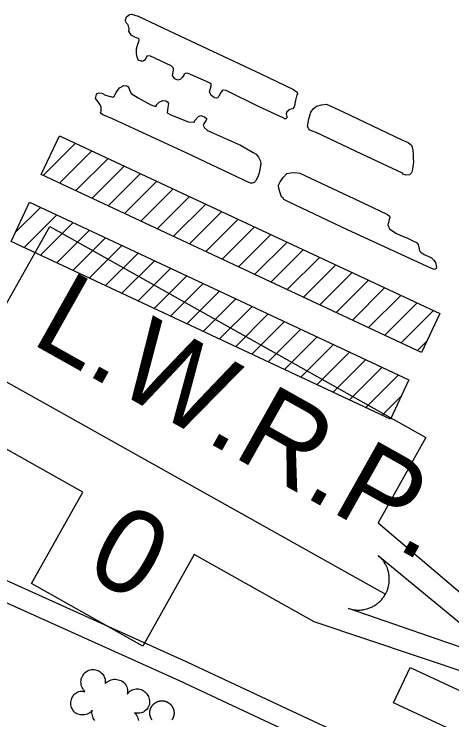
# Model space of a CAD drawing. Extents: x 3704301 to 3742427, y 506229 to 532009.
# Drawn here: x 3708834 to 3709482, y 524550 to 525595 of the extents above; entities that cross this region are included whole.
import ezdxf

# ---------------------------------------------------------------- set-up
doc = ezdxf.new("R2010")
doc.units = 0
for name, color, linetype in [('V-BLDG-OTLN', 7, 'Continuous'), ('V-ROAD-CNTR', 7, 'Continuous'), ('V-SITE-STRC', 7, 'Continuous'), ('V-TOPO-SHOR', 7, 'Continuous'), ('V-TOPO-WATR-IDEN', 7, 'Continuous')]:
    doc.layers.add(name, color=color, linetype=linetype)

msp = doc.modelspace()

# ---------------------------------------------------------------- linework, layer by layer
at = {"layer": 'V-BLDG-OTLN'}
for p, q in [((3708876.9, 525356.5), (3708924.6, 525404.2)), ((3708901, 525345.2), (3708948.7, 525392.9)), ((3708925.1, 525334), (3708972.8, 525381.7)), ((3708949.2, 525322.7), (3708996.9, 525370.4)), ((3708973.2, 525311.4), (3709020.9, 525359.1)), ((3708997.3, 525300.1), (3709045, 525347.8)), ((3709021.4, 525288.9), (3709069.1, 525336.6)), ((3709045.5, 525277.6), (3709093.2, 525325.3)), ((3709069.6, 525266.3), (3709117.3, 525314)), ((3708835.6, 525271.8), (3708872.9, 525309.2)), ((3709093.6, 525255.1), (3709141.3, 525302.8)), ((3708848.7, 525249.6), (3708897, 525297.9)), ((3709117.7, 525243.8), (3709165.4, 525291.5)), ((3708872.8, 525238.3), (3708921.1, 525286.6)), ((3709141.8, 525232.5), (3709189.5, 525280.2)), ((3708896.9, 525227), (3708945.2, 525275.3)), ((3708920.9, 525215.8), (3708969.2, 525264.1)), ((3709165.9, 525221.2), (3709213.6, 525268.9)), ((3708945, 525204.5), (3708993.3, 525252.8)), ((3709190, 525210), (3709237.7, 525257.7)), ((3708969.1, 525193.2), (3709017.4, 525241.5)), ((3709214.1, 525198.7), (3709261.8, 525246.4)), ((3708993.2, 525181.9), (3709041.5, 525230.2)), ((3709238.1, 525187.4), (3709285.8, 525235.1)), ((3709017.2, 525170.6), (3709065.5, 525218.9)), ((3709262.2, 525176.1), (3709309.9, 525223.8)), ((3709041.3, 525159.4), (3709089.6, 525207.7)), ((3709286.3, 525164.9), (3709334, 525212.6)), ((3709065.4, 525148.1), (3709113.7, 525196.4)), ((3709310.4, 525153.6), (3709358.1, 525201.3)), ((3709334.5, 525142.3), (3709382.2, 525190)), ((3709089.5, 525136.8), (3709137.8, 525185.1)), ((3709358.5, 525131), (3709406.2, 525178.7)), ((3709113.6, 525125.5), (3709161.9, 525173.8)), ((3709382.6, 525119.8), (3709430.3, 525167.5)), ((3709137.6, 525114.2), (3709185.9, 525162.5)), ((3709406.7, 525108.5), (3709454.4, 525156.2)), ((3709161.7, 525103), (3709210, 525151.3)), ((3709185.8, 525091.7), (3709234.1, 525140)), ((3709209.9, 525080.4), (3709258.2, 525128.7)), ((3709233.9, 525069.1), (3709282.2, 525117.4)), ((3709258, 525057.8), (3709306.3, 525106.2)), ((3709430.8, 525097.2), (3709444.7, 525111.1)), ((3709282.1, 525046.6), (3709330.4, 525094.9)), ((3709306.2, 525035.3), (3709354.5, 525083.6)), ((3709330.2, 525024), (3709378.5, 525072.3)), ((3709354.3, 525012.7), (3709402.6, 525061)), ((3709378.4, 525001.5), (3709406.9, 525030))]:
    msp.add_line(p, q, dxfattribs=at)
for points in [[(3709436.9, 525094.4), (3708874, 525357.9), (3708900.9, 525415.3), (3709463.8, 525151.8)], [(3709390.8, 524995.6), (3708829.4, 525258.6), (3708856.7, 525316.8), (3709418.1, 525053.8)], [(3709834.5, 524370.9), (3709395.4, 524575.2), (3709419.8, 524627.6), (3709858.8, 524423.3)]]:
    msp.add_lwpolyline(points, close=True, dxfattribs=at)
at = {"layer": 'V-ROAD-CNTR'}
for points in [[(3708720.9, 524802.3), (3709090.6, 524635.4), (3709485.6, 524450.5), (3709632.3, 524381.8), (3709704.7, 524349.8), (3709748.3, 524342.7), (3709809.3, 524355.6), (3709858.9, 524401.9), (3709903.2, 524473.9), (3709957, 524574.5), (3709982.2, 524650), (3709981.6, 524658.2), (3709966.1, 524672.8), (3709920, 524693.9), (3709756.7, 524768), (3709527.1, 524884)], [(3708708.6, 524774.9), (3709078.1, 524608.1), (3709472.9, 524423.3), (3709619.9, 524354.5), (3709696.1, 524320.8), (3709749, 524312.2), (3709823.6, 524328), (3709882.3, 524382.7), (3709929.2, 524459), (3709984.7, 524562.5), (3710012.6, 524646.3), (3710010.6, 524672.1), (3709983, 524698.1), (3709932.5, 524721.2), (3709769.7, 524795.1), (3709727, 524816.6)]]:
    msp.add_lwpolyline(points, dxfattribs=at)
at = {"layer": 'V-SITE-STRC'}
for points in [[(3708933.2, 524592.5), (3708934.9, 524592.4), (3708936.6, 524592.2), (3708938.3, 524591.7), (3708937.9, 524593.1), (3708936.5, 524594.6), (3708935.4, 524596.3), (3708934.4, 524598.1), (3708933.7, 524600), (3708933.1, 524601.9), (3708932.8, 524603.9), (3708932.7, 524606), (3708932.8, 524608), (3708933.1, 524610), (3708933.6, 524611.9), (3708934.4, 524613.8), (3708935.3, 524615.6), (3708936.4, 524617.3), (3708937.7, 524618.9), (3708939.2, 524620.3), (3708940.8, 524621.5), (3708942.5, 524622.6), (3708944.4, 524623.4), (3708946.3, 524624.1), (3708948.3, 524624.6), (3708950.2, 524624.7), (3708952.2, 524624.6), (3708954.2, 524624.3), (3708956.1, 524623.8), (3708957.9, 524623.1), (3708959.7, 524622.2), (3708961.3, 524621.1), (3708962.8, 524619.8), (3708964.2, 524618.4), (3708965.4, 524616.8), (3708966.5, 524615.1), (3708967.3, 524613.3), (3708967.9, 524611.5), (3708968.4, 524609.5), (3708968.6, 524607.6), (3708968.6, 524605.6), (3708968.4, 524603.6), (3708969.9, 524605.1), (3708971.6, 524606.4), (3708973.4, 524607.5), (3708975.3, 524608.5), (3708977.3, 524609.2), (3708979.4, 524609.7), (3708981.5, 524610), (3708983.6, 524610.1), (3708985.7, 524609.9), (3708987.8, 524609.5), (3708989.9, 524609), (3708991.8, 524608.2), (3708993.7, 524607.2), (3708995.5, 524606), (3708997.1, 524604.6), (3708998.4, 524602.9), (3708999.5, 524601), (3709000.4, 524599), (3709001, 524596.9), (3709001.4, 524594.7), (3709001.6, 524592.6), (3709001.5, 524590.4), (3709001.2, 524588.2), (3709002.4, 524589.7), (3709003.8, 524591.1), (3709005.3, 524592.4), (3709006.9, 524593.4), (3709008.6, 524594.3), (3709010.4, 524595), (3709012.3, 524595.5), (3709014.2, 524595.8), (3709016.2, 524595.8), (3709018.1, 524595.7), (3709020, 524595.3), (3709021.9, 524594.8), (3709023.7, 524594), (3709025.3, 524593.1), (3709026.9, 524592), (3709028.4, 524590.7), (3709029.7, 524589.3), (3709030.8, 524587.7), (3709031.8, 524586), (3709032.7, 524584.4), (3709033.4, 524582.6), (3709033.9, 524580.8), (3709034.3, 524578.9), (3709034.4, 524577), (3709034.3, 524575.2), (3709034, 524573.3), (3709033.5, 524571.5), (3709032.8, 524569.7), (3709031.9, 524568), (3709030.9, 524566.5), (3709029.6, 524565), (3709028.3, 524563.7), (3709026.7, 524562.6), (3709025.1, 524561.6), (3709023.4, 524560.9)], [(3708953.2, 524549.2), (3708952, 524550.9), (3708951, 524552.6), (3708950.2, 524554.5), (3708949.6, 524556.4), (3708949.2, 524558.4), (3708949, 524560.4), (3708949.1, 524562.4), (3708949.3, 524564.4), (3708948.5, 524562.9), (3708947.5, 524561.5), (3708945.8, 524560.4), (3708944, 524559.4), (3708942.1, 524558.6), (3708940.1, 524558), (3708938.1, 524557.6), (3708936.1, 524557.3), (3708934, 524557.3), (3708932, 524557.5), (3708930, 524557.9), (3708928, 524558.5), (3708926.1, 524559.3), (3708924.3, 524560.2), (3708922.8, 524561.6), (3708921.6, 524563.1), (3708920.5, 524564.8), (3708919.5, 524566.6), (3708918.8, 524568.4), (3708918.2, 524570.3), (3708917.9, 524572.3), (3708917.8, 524574.2), (3708917.8, 524576.2), (3708918.1, 524578.2), (3708918.6, 524580.1), (3708919.2, 524582), (3708920.1, 524583.8), (3708921.2, 524585.5), (3708922.4, 524587.1), (3708923.8, 524588.5), (3708925.1, 524589.6), (3708926.5, 524590.6), (3708928.1, 524591.3), (3708929.7, 524591.9), (3708931.4, 524592.3), (3708933.2, 524592.5)], [(3709034.6, 524560.1), (3709034.6, 524560.5), (3709034.7, 524560.8), (3709034.7, 524561.1), (3709034.7, 524561.4), (3709034.7, 524561.7), (3709034.7, 524562), (3709034.8, 524562.3), (3709034.8, 524562.6), (3709034.9, 524562.9), (3709034.9, 524563.3), (3709035, 524563.6), (3709035, 524563.9), (3709035.1, 524564.2), (3709035.2, 524564.5), (3709035.2, 524564.8), (3709035.3, 524565.1), (3709035.4, 524565.4), (3709035.5, 524565.7), (3709035.6, 524566), (3709035.7, 524566.3), (3709035.8, 524566.6), (3709035.9, 524566.9), (3709036, 524567.2), (3709036.1, 524567.4), (3709036.3, 524567.7), (3709036.4, 524568), (3709036.5, 524568.3), (3709036.7, 524568.6), (3709036.8, 524568.8), (3709037, 524569.1), (3709037.1, 524569.4), (3709037.3, 524569.7), (3709037.5, 524569.9), (3709037.6, 524570.2), (3709037.8, 524570.4), (3709038, 524570.7), (3709038.2, 524571), (3709038.4, 524571.2), (3709038.6, 524571.4), (3709038.8, 524571.7), (3709039, 524571.9), (3709039.2, 524572.2), (3709039.4, 524572.4), (3709039.6, 524572.6), (3709039.8, 524572.9), (3709040, 524573.1), (3709040.3, 524573.3), (3709040.5, 524573.5), (3709040.7, 524573.7), (3709041, 524573.9), (3709041.2, 524574.1), (3709041.4, 524574.3), (3709041.7, 524574.5), (3709041.9, 524574.7), (3709042.2, 524574.9), (3709042.5, 524575.1), (3709042.7, 524575.2), (3709043, 524575.4), (3709043.2, 524575.6), (3709043.5, 524575.7)], [(3709043.5, 524575.7), (3709043.8, 524575.9), (3709044.1, 524576), (3709044.3, 524576.2), (3709044.6, 524576.3), (3709044.9, 524576.5), (3709045.2, 524576.6), (3709045.5, 524576.7), (3709045.7, 524576.8), (3709046, 524577), (3709046.3, 524577.1), (3709046.6, 524577.2), (3709046.9, 524577.3), (3709047.2, 524577.4), (3709047.5, 524577.5), (3709047.8, 524577.5), (3709048.1, 524577.6), (3709048.4, 524577.7), (3709048.7, 524577.8), (3709049, 524577.8), (3709049.3, 524577.9), (3709049.7, 524577.9), (3709050, 524578), (3709050.3, 524578), (3709050.6, 524578.1), (3709050.9, 524578.1), (3709051.2, 524578.1), (3709051.5, 524578.2), (3709051.8, 524578.2), (3709052.1, 524578.2), (3709052.5, 524578.2), (3709052.8, 524578.2), (3709053.1, 524578.2), (3709053.4, 524578.2), (3709053.7, 524578.2), (3709054, 524578.1), (3709054.3, 524578.1), (3709054.6, 524578.1), (3709054.9, 524578), (3709055.3, 524578), (3709055.6, 524577.9), (3709055.9, 524577.9), (3709056.2, 524577.8), (3709056.5, 524577.8), (3709056.8, 524577.7), (3709057.1, 524577.6), (3709057.4, 524577.5), (3709057.7, 524577.4), (3709058, 524577.3), (3709058.3, 524577.2), (3709058.6, 524577.1), (3709058.9, 524577), (3709059.2, 524576.9), (3709059.5, 524576.8), (3709059.8, 524576.7), (3709060, 524576.6), (3709060.3, 524576.4), (3709060.6, 524576.3), (3709060.9, 524576.1), (3709061.2, 524576), (3709061.4, 524575.8), (3709061.7, 524575.7), (3709062, 524575.5), (3709062.2, 524575.4), (3709062.5, 524575.2), (3709062.8, 524575), (3709063, 524574.8), (3709063.3, 524574.7), (3709063.5, 524574.5), (3709063.8, 524574.3), (3709064, 524574.1), (3709064.2, 524573.9), (3709064.5, 524573.7), (3709064.7, 524573.5), (3709064.9, 524573.2), (3709065.2, 524573), (3709065.4, 524572.8), (3709065.6, 524572.6), (3709065.8, 524572.3), (3709066, 524572.1), (3709066.2, 524571.9), (3709066.4, 524571.6), (3709066.6, 524571.4), (3709066.8, 524571.1), (3709067, 524570.9), (3709067.2, 524570.6), (3709067.4, 524570.4), (3709067.5, 524570.1), (3709067.7, 524569.9), (3709067.9, 524569.6), (3709068, 524569.3), (3709068.2, 524569.1), (3709068.3, 524568.8), (3709068.5, 524568.5), (3709068.6, 524568.2), (3709068.8, 524567.9), (3709068.9, 524567.7), (3709069, 524567.4), (3709069.1, 524567.1), (3709069.3, 524566.8), (3709069.4, 524566.5)], [(3709023.4, 524560.9), (3709021.6, 524560.3), (3709019.7, 524559.9), (3709017.9, 524559.7), (3709016, 524559.8), (3709014.1, 524560), (3709012.2, 524560.4), (3709013.7, 524558.8), (3709014.9, 524557), (3709016, 524555.1), (3709016.8, 524553.2), (3709017.5, 524551.1), (3709017.9, 524549)], [(3709038, 524549.9), (3709037.8, 524550.1), (3709037.6, 524550.4), (3709037.4, 524550.7), (3709037.3, 524550.9), (3709037.1, 524551.2), (3709037, 524551.5), (3709036.8, 524551.7), (3709036.7, 524552), (3709036.5, 524552.3), (3709036.4, 524552.6), (3709036.2, 524552.9), (3709036.1, 524553.1), (3709036, 524553.4), (3709035.9, 524553.7), (3709035.8, 524554), (3709035.7, 524554.3), (3709035.6, 524554.6), (3709035.5, 524554.9), (3709035.4, 524555.2), (3709035.3, 524555.5), (3709035.2, 524555.8), (3709035.1, 524556.1), (3709035.1, 524556.4), (3709035, 524556.7), (3709034.9, 524557), (3709034.9, 524557.3), (3709034.8, 524557.6), (3709034.8, 524558), (3709034.8, 524558.3), (3709034.7, 524558.6), (3709034.7, 524558.9), (3709034.7, 524559.2), (3709034.7, 524559.5), (3709034.7, 524559.8), (3709034.6, 524560.1)], [(3709069.4, 524566.5), (3709069.5, 524566.2), (3709069.6, 524565.9), (3709069.7, 524565.6), (3709069.8, 524565.3), (3709069.9, 524565), (3709069.9, 524564.7), (3709070, 524564.4), (3709070.1, 524564.1), (3709070.1, 524563.8), (3709070.2, 524563.5), (3709070.3, 524563.2), (3709070.3, 524562.9), (3709070.4, 524562.6), (3709070.4, 524562.3), (3709070.4, 524561.9), (3709070.4, 524561.6), (3709070.5, 524561.3), (3709070.5, 524561), (3709070.5, 524560.7), (3709070.5, 524560.4), (3709070.5, 524560.1), (3709070.5, 524559.8), (3709070.5, 524559.4), (3709070.5, 524559.1), (3709070.4, 524558.8), (3709070.4, 524558.5), (3709070.4, 524558.2), (3709070.3, 524557.9), (3709070.3, 524557.6), (3709070.2, 524557.3), (3709070.2, 524557), (3709070.1, 524556.7), (3709070.1, 524556.3), (3709070, 524556), (3709069.9, 524555.7), (3709069.8, 524555.4), (3709069.8, 524555.1), (3709069.7, 524554.8), (3709069.6, 524554.5), (3709069.5, 524554.2), (3709069.4, 524554), (3709069.2, 524553.7), (3709069.1, 524553.4), (3709069, 524553.1), (3709068.9, 524552.8), (3709068.7, 524552.5), (3709068.6, 524552.2), (3709068.5, 524552), (3709068.3, 524551.7), (3709068.2, 524551.4), (3709068, 524551.1), (3709067.8, 524550.9), (3709067.7, 524550.6), (3709067.5, 524550.3), (3709067.3, 524550.1), (3709067.1, 524549.8)]]:
    msp.add_lwpolyline(points, dxfattribs=at)
at = {"layer": 'V-TOPO-SHOR'}
for points in [[(3709232.9, 525441.4), (3709195.5, 525458.8), (3709147.7, 525482.3), (3709143, 525482.8), (3709141.6, 525481.8), (3709139.2, 525479), (3709136.9, 525473.3), (3709135, 525471.4), (3709133.1, 525470.9), (3709130.2, 525471.4), (3709129.3, 525472.3), (3709125.5, 525475.1), (3709123.1, 525480.3), (3709125.5, 525489.3), (3709125.5, 525491.7), (3709123.1, 525493.6), (3709090.4, 525508.2), (3709087.1, 525507.7), (3709085.2, 525506.7), (3709084.8, 525504.8), (3709082.4, 525501.5), (3709080, 525499.2), (3709076.7, 525497.7), (3709073.4, 525498.7), (3709071.5, 525499.6), (3709068.2, 525504.3), (3709069.6, 525512.4), (3709069.6, 525515.2), (3709068.7, 525516.6), (3709066.3, 525519), (3709034.6, 525533.6), (3709030.3, 525533.1), (3709029.4, 525530.7), (3709028.9, 525529.8), (3709026.5, 525526.9), (3709024.7, 525525.5), (3709021.8, 525525.5), (3709020.4, 525526), (3709018, 525526.9), (3709016.1, 525531.6), (3709014.7, 525537.3), (3709014.7, 525543.9), (3709016.6, 525549.6), (3709018.4, 525554.8), (3709018.9, 525557.2), (3709018, 525559.1), (3709013.7, 525560.9), (3709007.1, 525564.2), (3709003.7, 525570.4), (3709004.2, 525573.7), (3709003.2, 525577.9), (3709002.3, 525580.3), (3708999.9, 525582.2), (3708998, 525586), (3708998.5, 525586.4), (3708999.9, 525591.2), (3709004.6, 525595), (3709007.5, 525595.4), (3709017.4, 525592.2), (3709071.8, 525566.8), (3709198.7, 525507), (3709247.5, 525483.9), (3709252.7, 525479.7), (3709253.2, 525477.3), (3709252.2, 525475.9), (3709250.4, 525467.9), (3709249.9, 525464.6), (3709249.4, 525463.6), (3709249.4, 525461.7), (3709248.5, 525457.9), (3709245.7, 525455.1), (3709241.9, 525454.1), (3709237.6, 525450.8), (3709236.2, 525447.5), (3709237.6, 525443.7), (3709237.6, 525441.8), (3709235.8, 525440.4), (3709234.3, 525440.4), (3709233.9, 525440.4), (3709232.9, 525441.4)], [(3709181.1, 525346.2), (3709088.3, 525389.9), (3708979.5, 525440.3), (3708965.3, 525446.4), (3708962.9, 525447.8), (3708961.9, 525449.7), (3708962.4, 525451.6), (3708962.4, 525457.7), (3708961.4, 525461), (3708958.1, 525465.3), (3708954.3, 525470.5), (3708955.7, 525476.2), (3708956.7, 525477.6), (3708959, 525479), (3708963.8, 525478.5), (3708969, 525475.2), (3708979.9, 525472.4), (3708981.7, 525473.9), (3708984.6, 525479.1), (3708989.8, 525486.2), (3708996.4, 525489.5), (3709000.6, 525489), (3709002, 525488.1), (3709003.5, 525486.2), (3709004.4, 525483.4), (3709006.8, 525477.7), (3709017.2, 525471.6), (3709036.2, 525461.2), (3709043.3, 525458.4), (3709044.7, 525460.3), (3709044.7, 525461.2), (3709048.4, 525465), (3709054.1, 525467.4), (3709058.4, 525466.9), (3709060.7, 525465.5), (3709062.2, 525463.2), (3709061.7, 525459.9), (3709061.2, 525457), (3709060.3, 525449.4), (3709065.5, 525446.2), (3709091.5, 525435.8), (3709100.5, 525435.4), (3709101.5, 525437.7), (3709106.7, 525443.9), (3709110, 525445.3), (3709115.6, 525443.4), (3709119, 525440.1), (3709118, 525438.2), (3709114.7, 525433), (3709113.8, 525430.7), (3709115.7, 525426.9), (3709119.9, 525423.1), (3709168.7, 525401.5), (3709187.6, 525390.2), (3709191.9, 525387.8), (3709195.7, 525383.6), (3709198.1, 525378.8), (3709199, 525374.6), (3709198.1, 525367.5), (3709196.7, 525360.4), (3709194.4, 525354.2), (3709192, 525350), (3709191.1, 525348.1), (3709189.2, 525346.2), (3709186.3, 525344.8), (3709183.5, 525345.2), (3709181.1, 525346.2)], [(3709408.6, 525360), (3709348.4, 525388.2), (3709280.7, 525420.2), (3709275.5, 525422.1), (3709271.7, 525423.5), (3709269.8, 525425.4), (3709267.9, 525429.1), (3709269.8, 525440.5), (3709273.1, 525450), (3709276.4, 525455.2), (3709281.1, 525459), (3709288.7, 525461.3), (3709296.2, 525461.8), (3709320.9, 525450.5), (3709407.5, 525409.1), (3709417, 525405.4), (3709421.7, 525401.1), (3709423.1, 525398.3), (3709424.1, 525393.6), (3709424.6, 525387.4), (3709424.6, 525382.2), (3709425.1, 525376.1), (3709424.1, 525369), (3709423.2, 525365.7), (3709422.3, 525361.9), (3709421.3, 525360), (3709419, 525357.6), (3709413.8, 525356.7), (3709409.5, 525358.5), (3709408.6, 525360)], [(3709450.5, 525219.1), (3709327.4, 525276.1), (3709239.8, 525317.5), (3709233.2, 525320.8), (3709231.8, 525322.7), (3709229.4, 525325), (3709228.9, 525326.4), (3709227.5, 525330.7), (3709225.6, 525337.3), (3709225.1, 525342), (3709227.5, 525347.2), (3709232.2, 525353.4), (3709237.4, 525359.1), (3709242.6, 525360.5), (3709249.2, 525361), (3709256.8, 525359.6), (3709353.3, 525314.4), (3709386.5, 525298.4), (3709389.3, 525296.1), (3709389.8, 525293.7), (3709388.9, 525291.3), (3709387, 525282.8), (3709388.9, 525278.6), (3709389.4, 525277.6), (3709398.8, 525271), (3709405.9, 525267.7), (3709414.9, 525264), (3709420.1, 525261.6), (3709425.8, 525258.8), (3709428.7, 525257.4), (3709429.6, 525256.5), (3709432, 525254.1), (3709432.9, 525250.3), (3709433.9, 525244.6), (3709435.8, 525242.8), (3709440.5, 525239.5), (3709447.6, 525236.6), (3709451.4, 525234.3), (3709455.2, 525231), (3709457.6, 525227.7), (3709459, 525220.6), (3709458.1, 525218.2), (3709455.7, 525217.3), (3709454.3, 525217.7), (3709450.5, 525219.1)]]:
    msp.add_lwpolyline(points, dxfattribs=at)
at = {"layer": 'V-TOPO-WATR-IDEN'}
msp.add_line((3708728.2, 525103.7), (3709383.2, 524736), dxfattribs=at)
for points in [[(3708524.9, 525248.2), (3708815.7, 525154.6), (3708886.5, 525280.8), (3709443.3, 524968.2), (3709372.5, 524842), (3709612.4, 524637.7)], [(3709586.5, 524591.5), (3709277.9, 524695.1), (3709100.5, 524794.7), (3709024.5, 524659.2), (3708859.6, 524751.8), (3708935.6, 524887.2), (3708739.5, 524997.3), (3708499, 525201.9)]]:
    msp.add_lwpolyline(points, dxfattribs=at)
msp.add_lwpolyline([(3709372.6, 524793.6), (3709568.5, 524632), (3709328.5, 524715.1), (3709332.9, 524713.8), (3709337.2, 524713), (3709339, 524712.8), (3709340.5, 524712.7), (3709342.4, 524712.6), (3709344.3, 524712.6), (3709345.9, 524712.7), (3709348, 524712.9), (3709350.3, 524713.2), (3709351.6, 524713.4), (3709353.3, 524713.7), (3709355.4, 524714.3), (3709357.1, 524714.7), (3709358.8, 524715.3), (3709360, 524715.8), (3709361.2, 524716.3), (3709362.7, 524716.9), (3709364.1, 524717.6), (3709365.4, 524718.3), (3709366.5, 524718.9), (3709368, 524719.9), (3709369.5, 524720.8), (3709370.6, 524721.7), (3709371.9, 524722.7), (3709373, 524723.6), (3709374, 524724.4), (3709374.7, 524725.1), (3709375.8, 524726.1), (3709376.9, 524727.2), (3709377.8, 524728.3), (3709378.8, 524729.5), (3709379.7, 524730.6), (3709380.6, 524731.8), (3709381.3, 524732.8), (3709382.2, 524734.3), (3709383.2, 524736), (3709383.5, 524736.5), (3709384, 524737.4), (3709384.5, 524738.3), (3709384.9, 524739.3), (3709385.3, 524740.3), (3709385.7, 524741.2), (3709386.2, 524742.3), (3709386.5, 524743.1), (3709386.8, 524744.2), (3709387.2, 524745.3), (3709387.4, 524746.1), (3709387.9, 524748), (3709388.1, 524749.1), (3709388.3, 524749.8), (3709388.5, 524751), (3709388.7, 524752.1), (3709388.8, 524753.2), (3709388.9, 524754.6), (3709389, 524755.8), (3709389.1, 524756.8), (3709389.1, 524757.6), (3709389.1, 524758.8), (3709389.1, 524759.8), (3709389, 524761), (3709388.9, 524762.2), (3709388.8, 524763.4), (3709388.6, 524765), (3709388.4, 524766.1), (3709388.2, 524767.3), (3709388, 524768.4), (3709387.7, 524769.4), (3709387.5, 524770.4), (3709387, 524771.9), (3709387, 524772), (3709386.7, 524772.9), (3709386.5, 524773.5), (3709386.2, 524774.5), (3709385.7, 524775.7), (3709385.3, 524776.6), (3709384.9, 524777.5), (3709384.4, 524778.5), (3709383.9, 524779.6), (3709383.5, 524780.3), (3709383, 524781.2), (3709382.2, 524782.5), (3709381.8, 524783.2), (3709381.4, 524783.8), (3709381.1, 524784.3), (3709380.6, 524784.9), (3709380.1, 524785.7), (3709379.5, 524786.5), (3709378.9, 524787.2), (3709378.2, 524788), (3709377.4, 524788.9), (3709376.9, 524789.5), (3709376.1, 524790.3), (3709375.1, 524791.3), (3709374.4, 524792), (3709373.8, 524792.5), (3709373.2, 524793), (3709372.8, 524793.3)], close=True, dxfattribs=at)

# ---------------------------------------------------------------- texts
for s, rotation, p in [('L.W.R.P.', 330.6945, (3708856.4, 525109.1)), ('0', 330.6946, (3708934.6, 524767.6))]:
    msp.add_text(s, height=124.5, rotation=rotation, dxfattribs=at).set_placement(p)

doc.saveas('drawing.dxf')
